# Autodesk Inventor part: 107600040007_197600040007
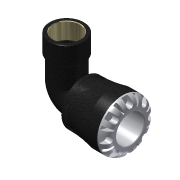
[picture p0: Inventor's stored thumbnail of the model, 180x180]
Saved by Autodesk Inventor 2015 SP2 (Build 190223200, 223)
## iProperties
Created: 2016-12
Part Number: 107600040007_197600040007
Material: PVC-Piping
Description: PLASSON 90° ELBOW WITH FEMALE INTEGRAL BRASS THREAD 40X3/4" SERIES 1
Document SubType Name: Modeling
Designer: KIM
Mass: 664.223 g
Surface Area: 733.008 cm^2
Volume: 474.445 cm^3
Density: 1.4 g/cm^3
Appearance: Black Cast
Author: KIM
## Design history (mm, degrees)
derived "1076.ipt"
feature "Solid1::1076.ipt"
tag "TaggingFeature1"
body "Solid1"
other parameters: "d1" = 30.24, "d8" = 61.6, "d13" = 8, "d14" = 8, "d15" = 0, "d17" = 360 deg, "d19" = 8 deg, "d20" = 0.8, "d21" = 0.8, "d22" = 8 deg, "d24" = 0, "d26" = 360 deg, "d33" = 7, "d51" = 0.7, "d54" = 14, "d55" = 8.8, "d57" = 15.68, "d58" = 0, "d74" = 0, "d78" = 72, "d82" = 0.8, "d115" = 360 deg, "d207" = 90 deg, "d228" = 11.9, "d248" = 4.32, "d270" = 107, "d279" = 51, "d281" = 3.61755, "d294" = 24.117, "d295" = 16, "d296" = 17.6, "d297" = 21.7053, "d299" = 28.21689, "d300" = 21.7053, "d301" = 0, "d302" = 0, "d306" = 1.56761, "d309" = 72.72, "d310" = 16.69156, "d312" = 15 deg, "d313" = 0.56, "d314" = 8.208, "d315" = 0.35, "l_" = 72, "A_" = 107, "A_1" = 51, "l_2" = 16, "Rp_" = 24.117, "d9" = 10, "d298" = 31.3521
